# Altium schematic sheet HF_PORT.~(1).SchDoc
size 431 x 279 mm; Date: Not shown in title block; ApprovedBy: Not shown in title block; CheckedBy: Not shown in title block; Author: Not shown in title block; CompanyName: Not shown in title block; DrawnBy: G. Fiolic; Engineer: Not shown in title block; Organization: Not shown in title block; Address1: Not shown in title block; Address2: Not shown in title block; Address3: Not shown in title block; Address4: Not shown in title block; DocumentNumber: 2; Revision: Use project parameter SCH_Rev; SheetNumber: 2; SheetTotal: 6; PageSetup: Record=PageOptions|CenterHorizontal=True|CenterVertical=True|PrintScale=1.00|XCorrection=1.00|YCorrection=1.00|PrintKind=0|BorderSize=5000000|LeftOffset=0|BottomOffset=0|Orientation=2|PaperLength=1000|PaperWidth=1000|Scale=100|PaperSource=15|PrintQuality=600|MediaType=1|DitherType=10|PaperKind=Letter|PrintScaleMode=1
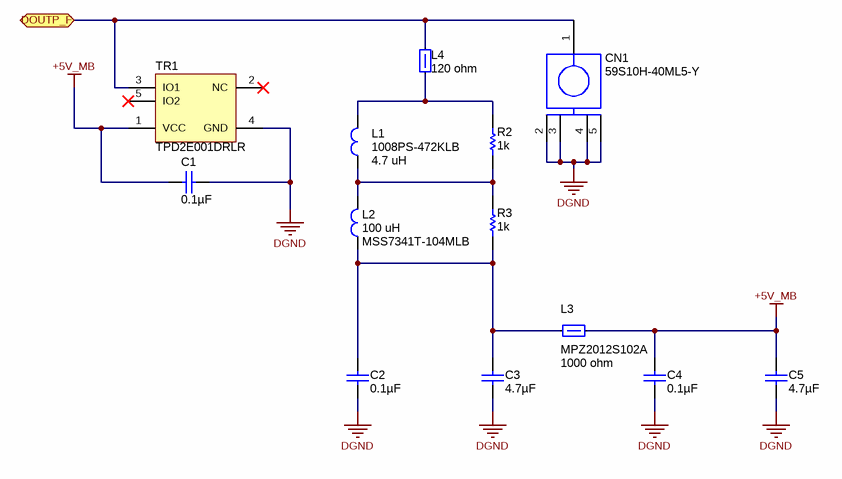
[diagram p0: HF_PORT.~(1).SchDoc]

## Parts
C1  ValueDisplayed: 0.1µF  [0402L]  (hidden comment: C1005X7R1H104K050BB)
C2  ValueDisplayed: 0.1µF  [0402L]  (hidden comment: GRM155R71C104KA88D)
C3  ValueDisplayed: 4.7µF  [0805]  (hidden comment: GRM21BR71C475KA73L)
C4  ValueDisplayed: 0.1µF  [0402L]  (hidden comment: GRM155R71C104KA88D)
C5  ValueDisplayed: 4.7µF  [0805]  (hidden comment: GRM21BR71C475KA73L)
CN1  59S10H-40ML5-Y  [59S10H-40ML5-Y]
L1  ValueDisplayed: 4.7 uH  [1008PS-472KLB]  (hidden comment: 1008PS-472KLB)
L2  ValueDisplayed: 100 uH  [MSS7341T-104MLB]  (hidden comment: MSS7341T-104MLB)
L3  MPZ2012S102A  value 1000 ohm  [0805]
L4  value 120 ohm  [0603]  (hidden comment: BLM18SG121TN1D)
R2  value 1k  [0603]  (hidden comment: RC0603FR-071KL)
R3  value 1k  [0603]  (hidden comment: RC0603FR-071KL)
TR1  TPD2E001DRLR  [DRL0005A]

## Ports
DOUTP_F

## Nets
+5V_MB: C1.1 C4.1 C5.1 L3.2 TR1.1(VCC)
DGND: C1.2 C2.2 C3.2 C4.2 C5.2 CN1.2 CN1.3 CN1.4 CN1.5 TR1.4(GND)
DOUTP_F: CN1.1 L4.2 TR1.3(IO1) ; port DOUTP_F
NetC2_1: C2.1 C3.1 L2.2 L3.1 R3.1
NetL1_1: L1.1 L2.1 R2.1 R3.2
NetL1_2: L1.2 L4.1 R2.2

Not connected (* = marked no-connect by the designer): TR1 2(NC)* 5(IO2)*

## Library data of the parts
C1 = C1005X7R1H104K050BB: CAP, CERM, 0.1uF, 50V, +/-10%, X7R, 0402; Manufacturer: TDK; Polarized: N; CompType: Capacitor; U/M: EA; Cap_F: 0.0000001; Tolerance_%: 10; Value1: Unknown; VDC_V: 50; TaMin_C: -55; TaMax_C: 125; Cap_Case: 0402
C2 C4 = GRM155R71C104KA88D: CAP, CERM, 0.1uF, 16V, +/-10%, X7R, 0402; Manufacturer: MuRata; Polarized: N; CompType: Capacitor; U/M: EA; Cap_F: 0.0000001; Tolerance_%: 10; Value1: Unknown; VDC_V: 16; TaMin_C: -55; TaMax_C: 125; Cap_Case: 0402
C3 C5 = GRM21BR71C475KA73L: CAP, CERM, 4.7uF, 16V, +/-10%, X7R, 0805; Manufacturer: MuRata; Polarized: N; CompType: Capacitor; U/M: EA; Cap_F: 0.0000047; Tolerance_%: 10; ESR_Ohm: 0.006; Value1: 0.006 ohm; VDC_V: 16; TaMin_C: -55; TaMax_C: 125
CN1 = 59S10H-40ML5-Y: Straight Plug PCB; Manufacturer: Rosenberger; SymbolVersion: use current date i.e. 2008-05-20; SymbolCreator: Use a-id; CompType: SMA connector; U/M: EA, IN, or GM
L1 = 1008PS-472KLB: Fixed Inductors Power Inductor 4.7 uH 10 % 0.95 A; Manufacturer: Coilcraft; Material: Ferrite; Maximum DC Current: 950 mA; Maximum DC Resistance: 350 mOhms; Q Minimum: 38; Self Resonant Frequency: 160 MHz; Shielding: Shielded; Tolerance_%: 10 %; Case Height: 2.74 mm; Case Length: 3.81 mm; Case Width: 3.78 mm; Test Frequency: 100 kHz
L2 = MSS7341T-104MLB: Fixed Inductors Power Inductor 100 uH 20 % 1.15 A; Manufacturer: Coilcraft; Material: Ferrite; Maximum DC Current: 1.15 A; Maximum DC Resistance: 310 mOhms; Self Resonant Frequency: 7.2 MHz; Shielding: Shielded; Tolerance_%: 20 %; Case Height: 4.1 mm; Case Length: 7.3 mm; Test Frequency: 100 kHz
L3 = Ferrite_Bead: 1.5A Ferrite Bead, 1000ohm @ 100MHz; Manufacturer: TDK Corporation; U/M: EA
L4 = BLM18SG121TN1D: 3A Ferrite Bead, 120 ohm @ 100MHz, SMD; Manufacturer: MuRata; Imax_A: 3; DCR_ohm: 0.025; Value1: 0.025 ohm; ZTyp@100MHz_Ohm: 120; U/M: EA
R2 R3 = RC0603FR-071KL: RES, 1.00k ohm, 1%, 0.1W, 0603; Manufacturer: Yageo; TempCo: ±100ppm/°C; Power_W: 0.1W, 1/10W
TR1 = TPD2E001DRLR: Low-Capacitance + / - 15 kV ESD-Protection Array for High-Speed Data Interfaces, 2 Channels, -40 to +85 degC, 5-pin SOT (DRL), Green (RoHS & no Sb/Br); Manufacturer: Texas Instruments; Alternate Manufacturer: None; Alternate PartNumber: Equivalent; Breakdown Voltage(Min)(V): 11; IEC 61000-4-2 Air-Gap(+/- kV): 15; IEC 61000-4-2 Contact(+/- kV): 8; IO Capacitance(Typ)(pF): 1.5; IO Leakage Current(nA): 1; SubFamily: ESD Solution; USB High Speed: TRUE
